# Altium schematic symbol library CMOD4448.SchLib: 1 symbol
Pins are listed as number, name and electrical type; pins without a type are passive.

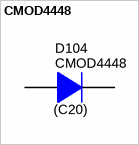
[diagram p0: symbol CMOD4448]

## CMOD4448
designator D104, comment (C20)  PartNumber: CMOD4448
Diode, Ultrafast, 75 V, 0.25 A, SOD-523; Manufacturer: Central Semiconductor; U/M: EA; Vf_V: 1.2; Value: 75V; Value1: 0.25A; Value2: 1.2V; Io_A: 0.25; Vr_V: 75; TJmax_C: 175
signal-integrity model Diode
simulation model CMDD4448
footprint sod-523 (NXP Semiconductor recommended land pattern, nominal STEP model)
pins: 1 K, 2 A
